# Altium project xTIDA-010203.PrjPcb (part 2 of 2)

## Sheet xTIDA-010203; CCMTLPFC_PowerStage.SchDoc
size A2; Date: Not shown in title block; ApprovedBy: Not shown in title block; CheckedBy: Not shown in title block; Author: Not shown in title block; CompanyName: Not shown in title block; Engineer: Not shown in title block; Organization: Not shown in title block; Address1: Not shown in title block; Address2: Not shown in title block; Address3: Not shown in title block; Address4: Not shown in title block; DocumentNumber: 2; Revision: Use project parameter SCH_Rev; SheetNumber: 2; SheetTotal: 4; PageSetup: Record=PageOptions¦CenterHorizontal=True¦CenterVertical=True¦PrintScale=1.00¦XCorrection=1.00¦YCorrection=1.00¦PrintKind=0¦BorderSize=5000000¦LeftOffset=0¦BottomOffset=0¦Orientation=2¦PaperLength=1000¦PaperWidth=1000¦Scale=100¦PaperSource=15¦PrintQuality=600¦MediaType=1¦DitherType=10¦PaperKind=Letter¦PrintScaleMode=1
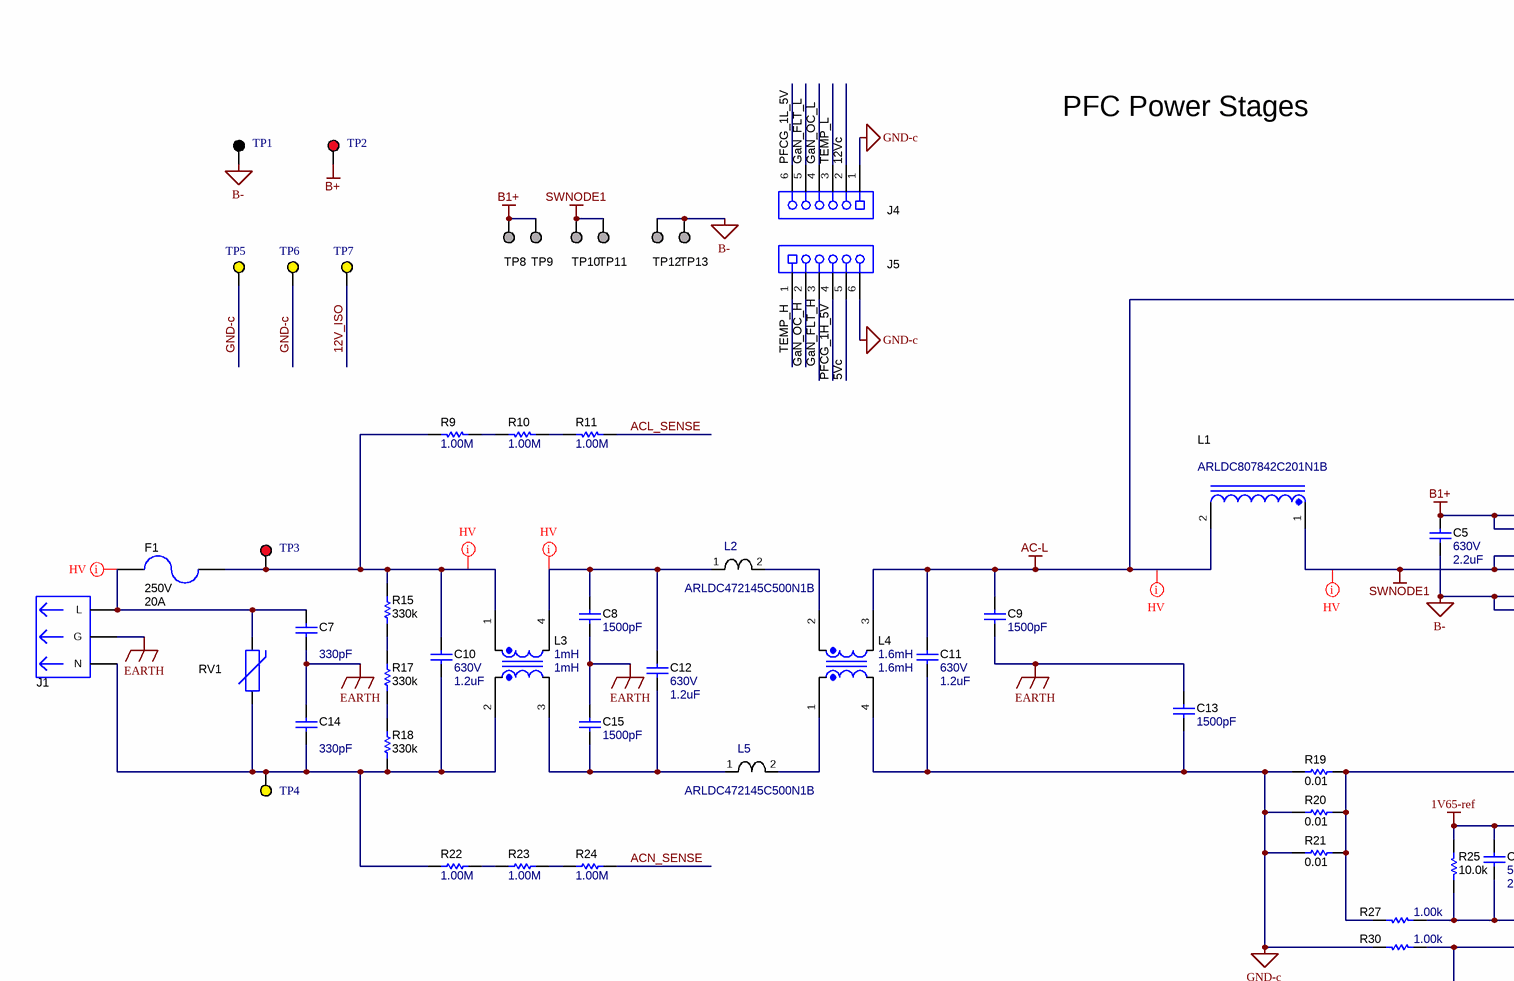
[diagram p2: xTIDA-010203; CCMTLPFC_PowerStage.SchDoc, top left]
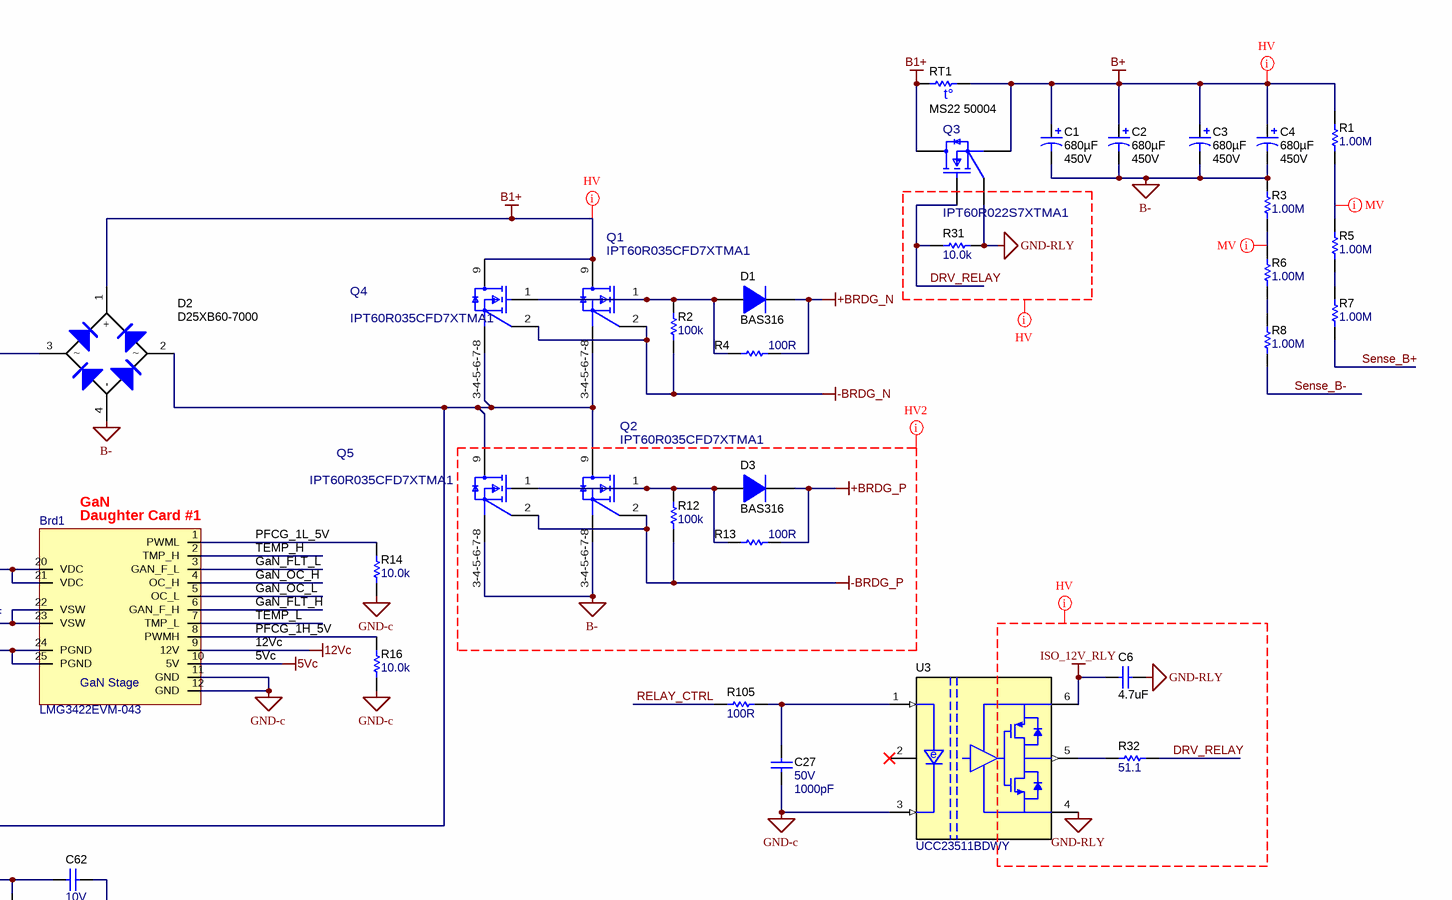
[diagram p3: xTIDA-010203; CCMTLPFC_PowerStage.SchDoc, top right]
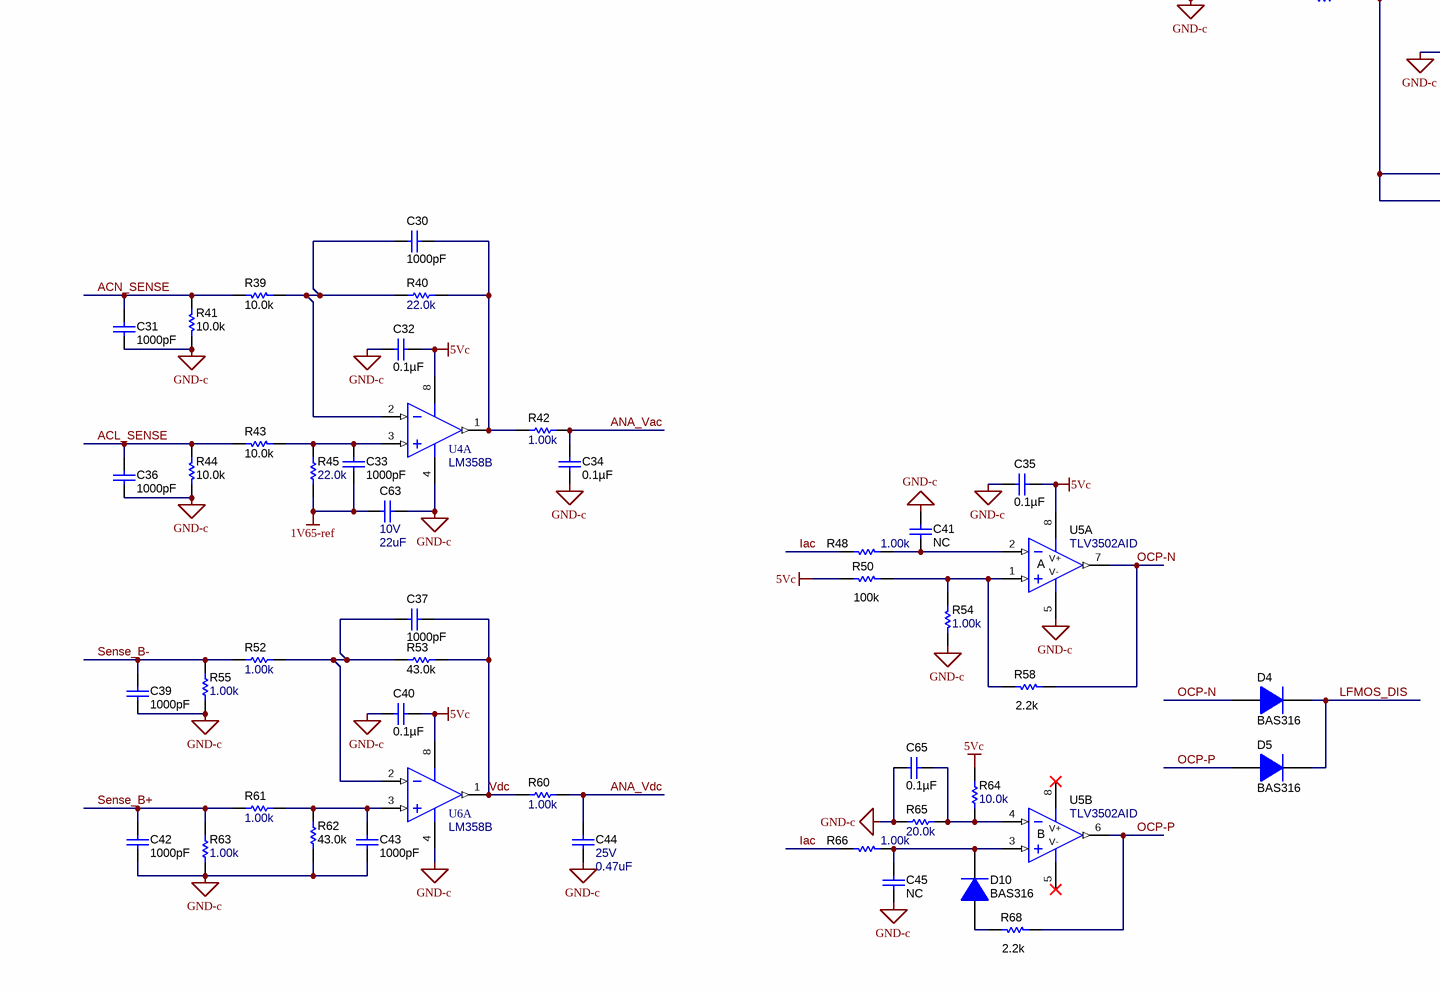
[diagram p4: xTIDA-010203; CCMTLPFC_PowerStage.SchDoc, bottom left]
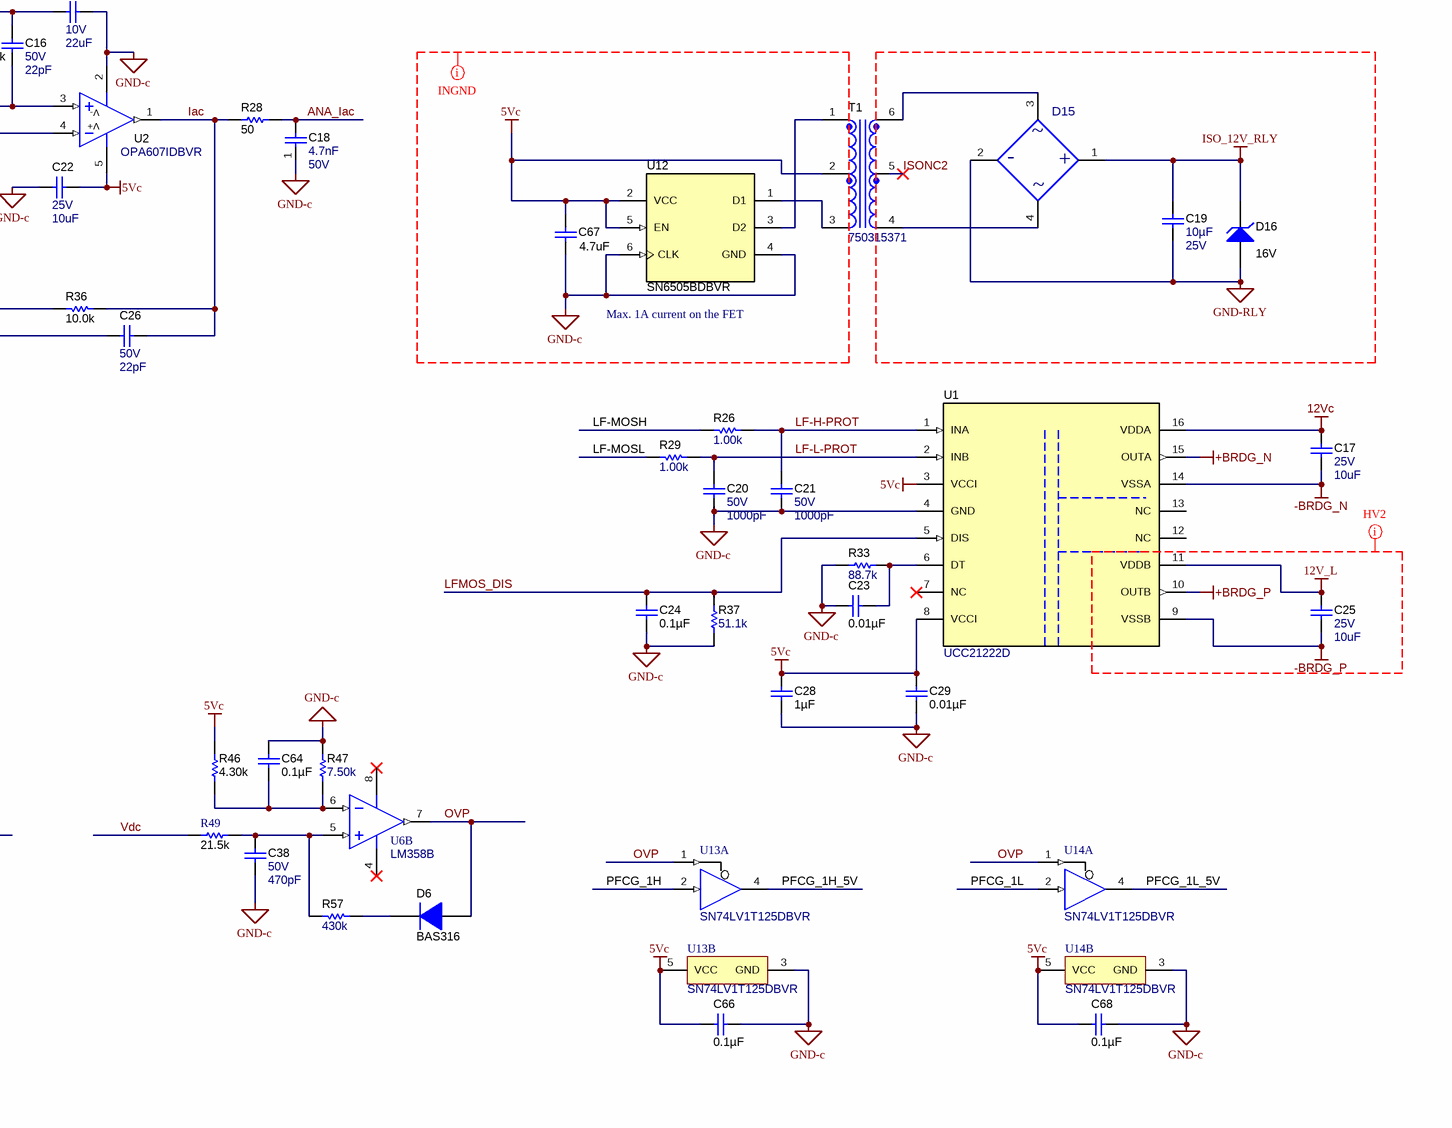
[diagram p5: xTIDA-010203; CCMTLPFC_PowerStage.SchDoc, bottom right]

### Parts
Brd1  LMG3422EVM-043  [HVP042E1]
C1  ValueDisplayed: 680µF  VDC_V: 450V  [WCAP-AI3H_3500x5700 - H]  (hidden comment: 450MXK680MEFCSN35X45)
C2  ValueDisplayed: 680µF  VDC_V: 450V  [WCAP-AI3H_3500x5700 - H]  (hidden comment: 450MXK680MEFCSN35X45)
C3  ValueDisplayed: 680µF  VDC_V: 450V  [WCAP-AI3H_3500x5700 - H]  (hidden comment: 450MXK680MEFCSN35X45)
C4  ValueDisplayed: 680µF  VDC_V: 450V  [WCAP-AI3H_3500x5700 - H]  (hidden comment: 450MXK680MEFCSN35X45)
C5  VDC_V: 630V  ValueDisplayed: 2.2uF  [B32924_24.5mm]  (hidden comment: ECWFG2J225)
C6  ValueDisplayed: 4.7uF  [0603]  (hidden comment: C1608X5R1V475K080AC)
C7  ValueDisplayed: 330pF  [KY_700x500x1000]  (hidden comment: DE2B3KY331KB3BU02F)
C8  ValueDisplayed: 1500pF  [CD45_800x600x1200]  (hidden comment: CD45-E2GA152M-NKA)
C9  ValueDisplayed: 1500pF  [CD45_800x600x1200]  (hidden comment: CD45-E2GA152M-NKA)
C10  VDC_V: 630V  ValueDisplayed: 1.2uF  [B32924_21.5mm]  (hidden comment: 890324027012)
C11  VDC_V: 630V  ValueDisplayed: 1.2uF  [B32924_21.5mm]  (hidden comment: 890324027012)
C12  VDC_V: 630V  ValueDisplayed: 1.2uF  [B32924_21.5mm]  (hidden comment: 890324027012)
C13  ValueDisplayed: 1500pF  [CD45_800x600x1200]  (hidden comment: CD45-E2GA152M-NKA)
C14  ValueDisplayed: 330pF  [KY_700x500x1000]  (hidden comment: DE2B3KY331KB3BU02F)
C15  ValueDisplayed: 1500pF  [CD45_800x600x1200]  (hidden comment: CD45-E2GA152M-NKA)
C16  VDC_V: 50V  ValueDisplayed: 22pF  [0603]  (hidden comment: CGA3E2C0G1H220J080AA)
C17  VDC_V: 25V  ValueDisplayed: 10uF  [0805_HV]  (hidden comment: GRM21BR61E106MA73L)
C18  Cap_F: 4.7nF  VDC_V: 50V  [0603]  (hidden comment: C0603C472J5RACTU)
C19  Cap_F: 10µF  VDC_V: 25V  [0805_HV]  (hidden comment: GRM21BZ71E106KE15L)
C20  VDC_V: 50V  ValueDisplayed: 1000pF  [0603]  (hidden comment: GCJ188R71H102KA01D)
C21  VDC_V: 50V  ValueDisplayed: 1000pF  [0603]  (hidden comment: GCJ188R71H102KA01D)
C22  VDC_V: 25V  ValueDisplayed: 10uF  [0805_HV]  (hidden comment: GRM21BR61E106MA73L)
C23  ValueDisplayed: 0.01µF  [0603]  (hidden comment: C0603X103K5RACTU)
C24  ValueDisplayed: 0.1µF  [0603]  (hidden comment: GRM188R71E104KA01D)
C25  VDC_V: 25V  ValueDisplayed: 10uF  [0805_HV]  (hidden comment: GRM21BR61E106MA73L)
C26  VDC_V: 50V  ValueDisplayed: 22pF  [0603]  (hidden comment: CGA3E2C0G1H220J080AA)
C27  VDC_V: 50V  ValueDisplayed: 1000pF  [0603]  (hidden comment: GCJ188R71H102KA01D)
C28  ValueDisplayed: 1µF  [0603]  (hidden comment: GRM185R60J105KE26D)
C29  ValueDisplayed: 0.01µF  [0603]  (hidden comment: C0603X103K5RACTU)
C30  ValueDisplayed: 1000pF  [0603]  (hidden comment: GRM188R71H102KA01D)
C31  ValueDisplayed: 1000pF  [0603]  (hidden comment: GRM188R71H102KA01D)
C32  ValueDisplayed: 0.1µF  [0603]  (hidden comment: GRM188R71E104KA01D)
C33  ValueDisplayed: 1000pF  [0603]  (hidden comment: GRM188R71H102KA01D)
C34  ValueDisplayed: 0.1µF  [0603]  (hidden comment: GRM188R71E104KA01D)
C35  ValueDisplayed: 0.1µF  [0603]  (hidden comment: GRM188R71E104KA01D)
C36  ValueDisplayed: 1000pF  [0603]  (hidden comment: GRM188R71H102KA01D)
C37  ValueDisplayed: 1000pF  [0603]  (hidden comment: GRM188R71H102KA01D)
C38  VDC_V: 50V  ValueDisplayed: 470pF  [0603]  (hidden comment: GRM188R71H471KA01D)
C39  ValueDisplayed: 1000pF  [0603]  (hidden comment: GRM188R71H102KA01D)
C40  ValueDisplayed: 0.1µF  [0603]  (hidden comment: GRM188R71E104KA01D)
C41  NC  [0603]  (no BOM)
C42  ValueDisplayed: 1000pF  [0603]  (hidden comment: GRM188R71H102KA01D)
C43  ValueDisplayed: 1000pF  [0603]  (hidden comment: GRM188R71H102KA01D)
C44  VDC_V: 25V  ValueDisplayed: 0.47uF  [0603]  (hidden comment: GRM188R61E474KA12D)
C45  NC  [0603]  (no BOM)
C62  VDC_V: 10V  ValueDisplayed: 22uF  [0603]  (hidden comment: C1608X5R1A226M080AC)
C63  VDC_V: 10V  ValueDisplayed: 22uF  [0603]  (hidden comment: C1608X5R1A226M080AC)
C64  ValueDisplayed: 0.1µF  [0603]  (hidden comment: GRM188R71E104KA01D)
C65  ValueDisplayed: 0.1µF  [0603]  (hidden comment: GRM188R71E104KA01D)
C66  ValueDisplayed: 0.1µF  [0603]  (hidden comment: GRM188R71E104KA01D)
C67  ValueDisplayed: 4.7uF  [0805_HV]  (hidden comment: GCM21BR71C475KA73L)
C68  ValueDisplayed: 0.1µF  [0603]  (hidden comment: GRM188R71E104KA01D)
D1  BAS316  [sod-323]
D2  D25XB60-7000  [5S]
D3  BAS316  [sod-323]
D4  BAS316  [sod-323]
D5  BAS316  [sod-323]
D6  BAS316  [sod-323]
D10  BAS316  [sod-323]
D15  KMB23STR  [FP-KMB23STR_SMT_4MM725_3MM85-MFG]  (value not drawn)
D16  value 16V  [SOD-123]  (hidden comment: BZT52C16-7-F)
F1  VAC_V: 250V  Irating_A: 20A  [FUSE_0325]  (hidden comment: 0325020.MXP)
J1  703W-00/54  [CONN_QUALTEK-703W-0054]  (value not drawn)  (mechanical)
J4  0448120024  [Molex_0448120024]  (value not drawn)
J5  0448120024  [Molex_0448120024]  (value not drawn)
L1  ARLDC807842C201N1B  [ARLDC807842C201N1B]
L2  ARLDC472145C500N1B  [ARLDC472145C500N1B]
L3  value 1mH  [ARCDC422740E102 N2B]  (hidden comment: ARCDC422740E102N2B)
L4  value 1.6mH  [ARCDC522747E152N2B]  (hidden comment: ARCDC522747E152N2B)
L5  ARLDC472145C500N1B  [ARLDC472145C500N1B]
Q1  IPT60R035CFD7XTMA1  [FP-IPT60R080G7XTMA1_HSOF-8-MFG]
Q2  IPT60R035CFD7XTMA1  [FP-IPT60R080G7XTMA1_HSOF-8-MFG]
Q3  IPT60R022S7XTMA1  [FP-IPT60R080G7XTMA1_HSOF-8-MFG]
Q4  IPT60R035CFD7XTMA1  [FP-IPT60R080G7XTMA1_HSOF-8-MFG]
Q5  IPT60R035CFD7XTMA1  [FP-IPT60R080G7XTMA1_HSOF-8-MFG]
R1  ValueDisplayed: 1.00M  [1206]  (hidden comment: RCV12061M00FKEA)
R2  ValueDisplayed: 100k  [0603]  (hidden comment: RC0603FR-07100KL)
R3  ValueDisplayed: 1.00M  [1206]  (hidden comment: RCV12061M00FKEA)
R4  ValueDisplayed: 100R  [0603]  (hidden comment: 100R 0603)
R5  ValueDisplayed: 1.00M  [1206]  (hidden comment: RCV12061M00FKEA)
R6  ValueDisplayed: 1.00M  [1206]  (hidden comment: RCV12061M00FKEA)
R7  ValueDisplayed: 1.00M  [1206]  (hidden comment: RCV12061M00FKEA)
R8  ValueDisplayed: 1.00M  [1206]  (hidden comment: RCV12061M00FKEA)
R9  ValueDisplayed: 1.00M  [1206]  (hidden comment: RCV12061M00FKEA)
R10  ValueDisplayed: 1.00M  [1206]  (hidden comment: RCV12061M00FKEA)
R11  ValueDisplayed: 1.00M  [1206]  (hidden comment: RCV12061M00FKEA)
R12  ValueDisplayed: 100k  [0603]  (hidden comment: RC0603FR-07100KL)
R13  ValueDisplayed: 100R  [0603]  (hidden comment: 100R 0603)
R14  ValueDisplayed: 10.0k  [0603]  (hidden comment: ERJ-3EKF1002V)
R15  ValueDisplayed: 330k  [1206]  (hidden comment: RV1206FR-07330KL)
R16  ValueDisplayed: 10.0k  [0603]  (hidden comment: ERJ-3EKF1002V)
R17  ValueDisplayed: 330k  [1206]  (hidden comment: RV1206FR-07330KL)
R18  ValueDisplayed: 330k  [1206]  (hidden comment: RV1206FR-07330KL)
R19  ValueDisplayed: 0.01  [1206]  (hidden comment: WSLP1206R0100FEA)
R20  ValueDisplayed: 0.01  [1206]  (hidden comment: WSLP1206R0100FEA)
R21  ValueDisplayed: 0.01  [1206]  (hidden comment: WSLP1206R0100FEA)
R22  ValueDisplayed: 1.00M  [1206]  (hidden comment: RCV12061M00FKEA)
R23  ValueDisplayed: 1.00M  [1206]  (hidden comment: RCV12061M00FKEA)
R24  ValueDisplayed: 1.00M  [1206]  (hidden comment: RCV12061M00FKEA)
R25  ValueDisplayed: 10.0k  [0603]  (hidden comment: CRCW060310K0FKEA)
R26  ValueDisplayed: 1.00k  [0603]  (hidden comment: ERJ-3EKF1001V)
R27  ValueDisplayed: 1.00k  [0603]  (hidden comment: ERJ-3EKF1001V)
R28  ValueDisplayed: 50  [0603]  (hidden comment: CRCW060350R0FKEA)
R29  ValueDisplayed: 1.00k  [0603]  (hidden comment: ERJ-3EKF1001V)
R30  ValueDisplayed: 1.00k  [0603]  (hidden comment: ERJ-3EKF1001V)
R31  ValueDisplayed: 10.0k  [0603]  (hidden comment: ERJ-3EKF1002V)
R32  ValueDisplayed: 51.1  [0603]  (hidden comment: RC0603FR-0751R1L)
R33  ValueDisplayed: 88.7k  [0603]  (hidden comment: CRCW060388K7FKEA)
R36  ValueDisplayed: 10.0k  [0603]  (hidden comment: CRCW060310K0FKEA)
R37  ValueDisplayed: 51.1k  [0603]  (hidden comment: RC0603FR-0751K1L)
R39  ValueDisplayed: 10.0k  [0603]  (hidden comment: CRCW060310K0FKEA)
R40  ValueDisplayed: 22.0k  [0603]  (hidden comment: ERJ-3EKF2202V)
R41  ValueDisplayed: 10.0k  [0603]  (hidden comment: CRCW060310K0FKEA)
R42  ValueDisplayed: 1.00k  [0603]  (hidden comment: ERJ-3EKF1001V)
R43  ValueDisplayed: 10.0k  [0603]  (hidden comment: CRCW060310K0FKEA)
R44  ValueDisplayed: 10.0k  [0603]  (hidden comment: CRCW060310K0FKEA)
R45  ValueDisplayed: 22.0k  [0603]  (hidden comment: ERJ-3EKF2202V)
R46  ValueDisplayed: 4.30k  [0603]  (hidden comment: RC0603FR-074K3L)
R47  ValueDisplayed: 7.50k  [0603]  (hidden comment: ERJ-3EKF7501V)
R48  ValueDisplayed: 1.00k  [0603]  (hidden comment: ERJ-3EKF1001V)
R49  value 21.5k  [0603]  (hidden comment: CRCW060321K5FKEA)
R50  100k  [0603]
R52  ValueDisplayed: 1.00k  [0603]  (hidden comment: CRCW06031K00FKEA)
R53  ValueDisplayed: 43.0k  [0603]  (hidden comment: RC0603FR-0743KL)
R54  ValueDisplayed: 1.00k  [0603]  (hidden comment: ERJ-3EKF1001V)
R55  ValueDisplayed: 1.00k  [0603]  (hidden comment: CRCW06031K00FKEA)
R57  ValueDisplayed: 430k  [0603]  (hidden comment: RC0603FR-07430KL)
R58  2.2k  [0603]
R60  ValueDisplayed: 1.00k  [0603]  (hidden comment: ERJ-3EKF1001V)
R61  ValueDisplayed: 1.00k  [0603]  (hidden comment: CRCW06031K00FKEA)
R62  ValueDisplayed: 43.0k  [0603]  (hidden comment: RC0603FR-0743KL)
R63  ValueDisplayed: 1.00k  [0603]  (hidden comment: CRCW06031K00FKEA)
R64  ValueDisplayed: 10.0k  [0603]  (hidden comment: ERJ-3EKF1002V)
R65  ValueDisplayed: 20.0k  [0603]  (hidden comment: RC0603FR-0720KL)
R66  ValueDisplayed: 1.00k  [0603]  (hidden comment: ERJ-3EKF1001V)
R68  2.2k  [0603]
R105  ValueDisplayed: 100R  [0603]  (hidden comment: 100R 0603)
RT1  MS22 50004  [MS2250004]
RV1  S10K275E2  [VAR_S10K275E2]  (value not drawn)
T1  750315371  [Wurth_750315371]
TP1  5001  [Keystone5001]  (value not drawn)  (no BOM)
TP2  5000  [Keystone5000]  (value not drawn)  (no BOM)
TP3  5000  [Keystone5000]  (value not drawn)  (no BOM)
TP4  5004  [Keystone5004]  (value not drawn)  (no BOM)
TP5  5004  [Keystone5004]  (value not drawn)  (no BOM)
TP6  GNDc  [Keystone5004]  (value not drawn)  (no BOM)
TP7  12Vc  [Keystone5004]  (value not drawn)  (no BOM)
TP8  Suggest using a net name here  [Mill-Max_0312-0-15-15-34-27-10-0]  (value not drawn)
TP9  Suggest using a net name here  [Mill-Max_0312-0-15-15-34-27-10-0]  (value not drawn)
TP10  Suggest using a net name here  [Mill-Max_0312-0-15-15-34-27-10-0]  (value not drawn)
TP11  Suggest using a net name here  [Mill-Max_0312-0-15-15-34-27-10-0]  (value not drawn)
TP12  Suggest using a net name here  [Mill-Max_0312-0-15-15-34-27-10-0]  (value not drawn)
TP13  Suggest using a net name here  [Mill-Max_0312-0-15-15-34-27-10-0]  (value not drawn)
U1  PartNumber: UCC21222D  [D0016A_N]  (hidden comment: UCC21222AD)
U2  OPA607IDBVR  [DBV0005A_N]
U3  UCC23511BDWY  [DWY0006A]
U4  LM358B  [D0008A_N]  (part A of 2)
U5  TLV3502AID  [D0008A_N]  (parts A,B of 2)
U6  PartNumber: LM358B  [D0008A_N]  (hidden comment: LM358AM)  (parts A,B of 2)
U12  SN6505BDBVR  [DBV0006A_N]
U13  SN74LV1T125DBVR  [DBV0005A_N]  (parts A,B of 2)
U14  SN74LV1T125DBVR  [DBV0005A_N]  (parts A,B of 2)

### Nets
1V65-ref: C16.1 C33.2 C62.1 C63.1 R25.2 R45.2
5Vc: Brd1.10(5V) C22.2 C28.1 C29.1 C32.2 C35.2 C40.2 C66.1 C67.1 C68.1 J5.5 R46.2 R50.1 R64.2 T1.2 U1.3(VCCI) U1.8(VCCI) U2.5(V+) U4.8(V+) U5.8(V+) U6.8(V+) U12.2(VCC) U12.5(EN) U13.5(VCC) U14.5(VCC)
12V_L: C25.1 U1.11(VDDB)
12Vc: Brd1.9(12V) C17.1 J4.2 U1.16(VDDA)
+BRDG_N: D1.1(K) R4.1 U1.15(OUTA)
+BRDG_P: D3.1(K) R13.1 U1.10(OUTB)
-BRDG_N: C17.2 Q1.2(Driver_Source) Q4.2(Driver_Source) R2.1 U1.14(VSSA)
-BRDG_P: C25.2 Q2.2(Driver_Source) Q5.2(Driver_Source) R12.1 U1.9(VSSB)
AC-L: C9.1 C11.1 D2.3 L1.2 L4.3
B1+: Brd1.20(VDC) Brd1.21(VDC) C5.1 D2.1(+) Q1.9(Drain) Q3.9(Drain) Q4.9(Drain) RT1.1 TP8.1 TP9.1
B+: C1.1(+) C2.1(+) C3.1(+) C4.1(+) Q3.3-4-5-6-7-8(Source) R1.2 RT1.2 TP2.1
B-: Brd1.24(PGND) Brd1.25(PGND) C1.2(-) C2.2(-) C3.2(-) C4.2(-) C5.2 D2.4(-) Q2.3-4-5-6-7-8(Source) Q5.3-4-5-6-7-8(Source) R3.2 TP1.1 TP12.1 TP13.1
EARTH: C7.2 C8.2 C9.2 C13.1 C14.1 C15.1 J1.3(G)
GND-c: Brd1.11(GND) Brd1.12(GND) C11.2 C13.2 C18.1 C20.2 C21.1 C22.1 C23.2 C24.1 C27.1 C28.2 C29.2 C31.2 C32.1 C34.1 C35.1 C36.2 C38.2 C39.2 C40.1 C41.2 C42.2 C43.1 C44.1 C45.1 C62.2 C63.2 C64.1 C65.2 C66.2 C67.2 C68.2 J4.1 J5.6 L4.4 R14.2 R16.2 R19.1 R20.1 R21.1 R30.2 R33.2 R37.1 R41.1 R44.1 R47.2 R54.2 R55.2 R62.1 R63.1 R65.2 TP5.1 TP6.1 U1.4(GND) U2.2(V-) U3.3(Cathode) U4.4(GND) U5.5(V-) U6.4(GND) U12.4(GND) U12.6(CLK) U13.3(GND) U14.3(GND)
GND-RLY: C6.2 C19.2 D15.2(-) D16.2(A) Q3.2(Driver_Source) R31.1 U3.4(VSS)
ISO_12V_RLY: C6.1 C19.1 D15.1(+) D16.1(K) U3.6(Vout)
SWNODE1: Brd1.22(VSW) Brd1.23(VSW) L1.1 TP10.1 TP11.1
12V_ISO: TP7.1
ACL_SENSE: C36.1 R11.2 R43.1 R44.2
ACN_SENSE: C31.1 R24.2 R39.1 R41.2
ANA_Iac: C18.2 R28.2
ANA_Vac: C34.2 R42.1
ANA_Vdc: C44.2 R60.1
DRV_RELAY: Q3.1(Gate) R31.2 R32.2
GaN_FLT_H: Brd1.6(GAN_F_H) J5.3
GaN_FLT_L: Brd1.3(GAN_F_L) J4.5
GaN_OC_H: Brd1.4(OC_H) J5.2
GaN_OC_L: Brd1.5(OC_L) J4.4
Iac: C26.1 R28.1 R36.1 R48.2 R66.2 U2.1(OUT)
ISONC2: T1.5
LF-H-PROT: C21.2 R26.1 U1.1(INA)
LF-L-PROT: C20.1 R29.1 U1.2(INB)
LF-MOSH: R26.2
LF-MOSL: R29.2
LFMOS_DIS: C24.2 D4.1(K) D5.1(K) R37.2 U1.5(DIS)
OCP-N: D4.2(A) R58.2 U5.7(OUT_A)
OCP-P: D5.2(A) R68.2 U5.6(OUT_B)
OVP: D6.2(A) U6.7(OUTB) U13.1(~{OE}) U14.1(~{OE})
PFCG_1H: U13.2(A)
PFCG_1H_5V: Brd1.8(PWMH) J5.4 R16.1 U13.4(Y)
PFCG_1L: U14.2(A)
PFCG_1L_5V: Brd1.1(PWML) J4.6 R14.1 U14.4(Y)
RELAY_CTRL: R105.2
Sense_B+: C42.1 R7.1 R61.1 R63.2
Sense_B-: C39.1 R8.1 R52.2 R55.1
TEMP_H: Brd1.2(TMP_H) J5.1
TEMP_L: Brd1.7(TMP_L) J4.3
Vdc: C37.2 R49.2 R53.2 R60.2 U6.1(OUTA)
NetC7_1: C7.1 F1.2 J1.1(L) RV1.2
NetC8_1: C8.1 C12.1 L2.1 L3.4
NetC10_1: C10.1 F1.1 L3.1 R9.1 R15.2 TP3.1
NetC10_2: C10.2 C14.2 J1.2(N) L3.2 R18.1 R22.1 RV1.1 TP4.1
NetC12_2: C12.2 C15.2 L3.3 L5.1
NetC16_2: C16.2 R25.1 R27.1 U2.3(IN+)
NetC23_1: C23.1 R33.1 U1.6(DT)
NetC26_2: C26.2 R30.1 R36.2 U2.4(IN-)
NetC27_2: C27.2 R105.1 U3.1(Anode)
NetC30_1: C30.1 R39.2 R40.2 U4.2(INA-)
NetC30_2: C30.2 R40.1 R42.2 U4.1(OUTA)
NetC33_1: C33.1 R43.2 R45.1 U4.3(INA+)
NetC37_1: C37.1 R52.1 R53.1 U6.2(INA-)
NetC38_1: C38.1 R49.1 R57.2 U6.5(INB+)
NetC41_1: C41.1 R48.1 U5.2(-IN_A)
NetC43_2: C43.2 R61.2 R62.2 U6.3(INA+)
NetC45_2: C45.2 D10.1(K) R66.1 U5.3(+IN_B)
NetC64_2: C64.2 R46.1 R47.1 U6.6(INB-)
NetC65_1: C65.1 R64.1 R65.1 U5.4(-IN_B)
NetD1_2: D1.2(A) Q1.1(Gate) Q4.1(Gate) R2.2 R4.2
NetD2_2: D2.2 Q1.3-4-5-6-7-8(Source) Q2.9(Drain) Q4.3-4-5-6-7-8(Source) Q5.9(Drain) R19.2 R20.2 R21.2 R27.2
NetD3_2: D3.2(A) Q2.1(Gate) Q5.1(Gate) R12.2 R13.2
NetD6_1: D6.1(K) R57.1
NetD10_2: D10.2(A) R68.1
NetD15_3: D15.3(1_~) T1.6
NetD15_4: D15.4(2_~) T1.4
NetL2_2: L2.2 L4.2
NetL4_1: L4.1 L5.2
NetR1_1: R1.1 R5.2
NetR3_1: R3.1 R6.2
NetR5_1: R5.1 R7.2
NetR6_1: R6.1 R8.2
NetR9_2: R9.2 R10.1
NetR10_2: R10.2 R11.1
NetR15_1: R15.1 R17.2
NetR17_1: R17.1 R18.2
NetR22_2: R22.2 R23.1
NetR23_2: R23.2 R24.1
NetR32_1: R32.1 U3.5(Vout)
NetR50_2: R50.2 R54.1 R58.1 U5.1(+IN_A)
NetT1_1: T1.1 U12.3(D2)
NetT1_3: T1.3 U12.1(D1)

Not connected (* = marked no-connect by the designer): U1 7(NC)* 12(NC) 13(NC); U3 2(NC)*

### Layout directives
net class HV: AC-L, B1+, B+, NetC7_1, NetC8_1, NetC10_1, SWNODE1
net class MV: 12V_L, +BRDG_P, -BRDG_P, B-, DRV_RELAY, GND-RLY, ISO_12V_RLY, NetR1_1, NetR3_1
net class INGND: 5Vc, GND-c

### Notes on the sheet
- PFC Power Stages
- (near Brd1) GaN
- (near Brd1) Daughter Card #1
- Max. 1A current on the FET

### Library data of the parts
Brd1 = Brd- GaN: GaN daughter card with LMG342xR030; Manufacturer: TEXAS INSTRUMENTS; SymbolCreator: Use LDAP id; SymbolVersion: use current date i.e. 2008-05-20
C1-C4 = CMP-0084882-1: CAP, AL, 680 µF, 450 V, +/- 20%, TH; Manufacturer: Rubycon; SizeY_mm: 35; CompType: Capacitor; U/M: EA; SizeZ_mm: 45; SizeAreaWB_mm2: 1369; SizeArea_mm2: 1225; TaMax_C: 105°C; AEC Category: Q200; Cap_Case: 35x57mm; TaMin_C: -25°C; AEC Qualified: N; Value: 680uF; Polarized: Y
C5 = CMP-0012436-3: CAP, Film, 2.2 uF, 630 V, +/- 20%, TH; Manufacturer: Panasonic; Polarized: N; SizeAreaWB_mm2: 536; Value1: Unknown; Value: 2.2uF; TaMax_C: 110°C; SizeZ_mm: 24.5; SizeX_mm: 12; SizeY_mm: 31.5; SizeArea_mm2: 441; Cap_F: 2.2µF; AEC Category: Q200
C6 = CMP-0007022-5: CAP, CERM, 4.7 uF, 35 V, +/- 10%, X5R, 0603; Manufacturer: TDK; TaMin_C: -55°C; ESR_ohm: 3.728m; Polarized: N; SizeAreaWB_mm2: 4.68; Value1: 0.003728 ohm; U/M: EA; Value: 4.7uF; TaMax_C: 85°C; SizeZ_mm: 1; SizeX_mm: 1.6; SizeY_mm: 0.8; Value2: 35V; SizeArea_mm2: 1.28; CompType: Capacitor; Cap_F: 4.7µF; IRMS_A: 2.69359A; AEC Category: Q200
C7 C14 = CMP-0009608-4: CAP, CERM, 330 pF, X1 250 VAC/Y2 300 VAC, +/- 10%, B, TH; Manufacturer: MuRata; TaMin_C: -25°C; Polarized: N; SizeAreaWB_mm2: 66.5; Value1: Unknown; U/M: EA; Value: 330pF; TaMax_C: 85°C; SizeZ_mm: 10; SizeX_mm: 7.5; SizeY_mm: 5; Cap_Case: 7x5x10mm; SizeArea_mm2: 37.5; AEC Category: Q200; AC_Safety: X1Y2; VAC_X: 250V; VAC_Y: 300V
C8 C9 C13 C15 = CMP-0009596-2: CAP, CERM, 1500 pF,  V, +/- 20%, E, D8xT6mm; Manufacturer: TDK; TaMin_C: -25°C; Polarized: N; SizeAreaWB_mm2: 101.2; Value1: Unknown; U/M: EA; Value: 1500pF; TaMax_C: 125°C; SizeZ_mm: 12; SizeX_mm: 10.65; SizeY_mm: 6; Cap_Case: 8x6x12mm; SizeArea_mm2: 63.9; Cap_F: 1.5nF; AEC Category: Q200
C10-C12 = CMP-0012433-1: CAP, Film, 1.2 uF, 630 V, +/- 10%, 0.017 ohm, TH; Manufacturer: Wurth Elktronik; ESR_ohm: 0.017; Polarized: N; SizeAreaWB_mm2: 485.75; U/M: EA; Value: 1.2uF; TaMax_C: 110°C; SizeZ_mm: 21.5; SizeX_mm: 12.5; SizeY_mm: 31.5; SizeArea_mm2: 393.75; Cap_F: 1.2µF; IRMS_A: 146mA; AEC Category: Q200
C16 C26 = CMP-0007071-1: CAP, CERM, 22 pF, 50 V, +/- 5%, C0G/NP0, AEC-Q200 Grade 1, 0603; Manufacturer: TDK; TaMin_C: -55°C; Polarized: N; SizeAreaWB_mm2: 4.68; Value1: Unknown; U/M: EA; Value: 22pF; TaMax_C: 125°C; SizeZ_mm: 1; SizeX_mm: 1.6; SizeY_mm: 0.8; SizeArea_mm2: 1.28; AEC Qualified: Y; AEC Category: Q200
C17 C22 C25 = CMP-0008378-2: CAP, CERM, 10 uF, 25 V, +/- 10%, X5R, 0805; Manufacturer: MuRata; TaMin_C: -55°C; Polarized: N; SizeAreaWB_mm2: 6.75; Value1: Unknown; U/M: EA; Value: 10uF; TaMax_C: 85°C; SizeZ_mm: 1.45; SizeX_mm: 2; SizeY_mm: 1.25; Cap_Case: 0805; SizeArea_mm2: 2.5; Cap_F: 10µF; AEC Category: Q200
C18 = CMP-0006942-1: CAP, CERM, 4700 pF, 50 V, +/- 5%, X7R, 0603; Manufacturer: Kemet; TaMin_C: -55°C; Polarized: N; SizeAreaWB_mm2: 4.68; Value1: Unknown; U/M: EA; Value: 4700pF; TaMax_C: 125°C; SizeZ_mm: 1; SizeX_mm: 1.6; SizeY_mm: 0.8; SizeArea_mm2: 1.28; AEC Category: Q200
C19 = CMP-0008378-1: CAP, CERM, 10 uF, 25 V, +/- 10%, X7R, 0805; Manufacturer: MuRata; TaMin_C: -55°C; Polarized: N; SizeAreaWB_mm2: 6.75; Value1: Unknown; U/M: EA; Value: 10uF; TaMax_C: 125°C; SizeZ_mm: 1.45; SizeX_mm: 2; SizeY_mm: 1.25; Cap_Case: 0805; SizeArea_mm2: 2.5; AEC Category: Q200
C20 C21 C27 = CMP-0007432-5: CAP, CERM, 1000 pF, 50 V, +/- 10%, X7R, 0603; Manufacturer: MuRata; TaMin_C: -55°C; Polarized: N; SizeAreaWB_mm2: 4.68; Value1: Unknown; U/M: EA; Value: 1000pF; TaMax_C: 125°C; SizeZ_mm: 1; SizeX_mm: 1.6; SizeY_mm: 0.8; SizeArea_mm2: 1.28; Cap_F: 1nF; AEC Category: Q200
C23 C29 = C0603X103K5RACTU: CAP, CERM, 0.01uF, 50V, +/-10%, X7R, 0603; Manufacturer: Kemet; Polarized: N; CompType: Capacitor; U/M: EA; Cap_F: 0.00000001; Tolerance_%: 10; Value1: Unknown; VDC_V: 50; TaMin_C: -55; TaMax_C: 125
C24 C32 C34 C35 C40 C41 C45 C64-C66 C68 = GRM188R71E104KA01D: CAP, CERM, 0.1 µF, 25 V,+/- 10%, X7R, 0603; Manufacturer: MuRata; Polarized: N; CompType: Capacitor; Value: 0.1uF; U/M: EA; Cap_F: 0.0000001; Tolerance_%: 10; VDC_V: 25; Value2: 25V; TaMin_C: -55; TaMax_C: 125; SizeArea_mm2: 1.28; SizeAreaWB_mm2: 4.68; SizeX_mm: 1.6; SizeY_mm: 0.8; SizeZ_mm: 1; AEC Category: Q200; Green_Lifecycle: Active; Green_REACh: Passed
C28 = GRM185R60J105KE26D: CAP, CERM, 1uF, 6.3V, +/-10%, X5R, 0603; Manufacturer: MuRata; Polarized: N; CompType: Capacitor; U/M: EA; Cap_F: 0.000001; Tolerance_%: 10; Value1: Unknown; VDC_V: 6.3; TaMin_C: -55; TaMax_C: 85
C30 C31 C33 C36 C37 C39 C42 C43 = GRM188R71H102KA01D: CAP, CERM, 1000 pF, 50 V,+/- 10%, X7R, 0603; Manufacturer: MuRata; Polarized: N; CompType: Capacitor; Value: 1000pF; U/M: EA; Cap_F: 0.000000001; Tolerance_%: 10; VDC_V: 50; Value2: 50V; TaMin_C: -55; TaMax_C: 125; SizeArea_mm2: 1.28; SizeAreaWB_mm2: 4.68; SizeX_mm: 1.6; SizeY_mm: 0.8; SizeZ_mm: 1; AEC Category: Q200; Green_Lifecycle: Active; Green_REACh: Passed
C38 = CMP-0007455-4: CAP, CERM, 470 pF, 50 V, +/- 10%, X7R, 0603; Manufacturer: MuRata; TaMin_C: -55°C; Polarized: N; SizeAreaWB_mm2: 4.68; Value1: Unknown; U/M: EA; Value: 470pF; TaMax_C: 125°C; SizeZ_mm: 1; SizeX_mm: 1.6; SizeY_mm: 0.8; SizeArea_mm2: 1.28; AEC Category: Q200
C44 = CMP-0007346-2: CAP, CERM, 0.47 uF, 25 V, +/- 10%, X5R, 0603; Manufacturer: MuRata; TaMin_C: -55°C; Polarized: N; SizeAreaWB_mm2: 4.68; Value1: Unknown; U/M: EA; Value: 0.47uF; TaMax_C: 85°C; SizeZ_mm: 1; SizeX_mm: 1.6; SizeY_mm: 0.8; SizeArea_mm2: 1.28; Cap_F: 470nF; AEC Category: Q200
C62 C63 = CMP-0007005-1: CAP, CERM, 22 uF, 10 V, +/- 20%, X5R, 0603; Manufacturer: TDK; TaMin_C: -55°C; ESR_ohm: 3.71m; Polarized: N; SizeAreaWB_mm2: 4.68; Value1: 0.00371 ohm; U/M: EA; Value: 22uF; TaMax_C: 85°C; SizeZ_mm: 1; SizeX_mm: 1.6; SizeY_mm: 0.8; SizeArea_mm2: 1.28; Cap_F: 22µF; IRMS_A: 2.69936A; AEC Category: Q200
C67 = CMP-0008020-2: CAP, CERM, 4.7 uF, 16 V, +/- 10%, X7R, AEC-Q200 Grade 1, 0805; Manufacturer: MuRata; TaMin_C: -55°C; Polarized: N; SizeAreaWB_mm2: 6.75; Value1: Unknown; U/M: EA; Value: 4.7uF; TaMax_C: 125°C; SizeZ_mm: 1.45; SizeX_mm: 2; SizeY_mm: 1.25; Cap_Case: 0805; Value2: 16V; SizeArea_mm2: 2.5; AEC Qualified: Y; Cap_F: 4.7µF; AEC Grade: 1; AEC Category: Q200
D1 D3-D6 D10 = BAS316,115: Diode, Ultrafast, 100 V, 0.25 A, SOD-323; Manufacturer: Toshiba; U/M: EA; Vf_V: 1.4; Value: 100V; Value1: 0.25A; Value2: 1.4V; Io_A: 0.25; Vr_V: 100; TJmax_C: 150
D2 = D25XB60-7000: Diode, Switching-Bridge, 800 V, 25 A, TH; Manufacturer: Shindengen; U/M: EA; Vf_V: 1.05; Value: 600V; Value1: 3.5A; Value2: 1.05V; Io_A: 3.5; Vr_V: 600; TJmax_C: 150
D15 = CMP-0089345-2: Bridge Rectifier Single Phase Schottky 30V Surface Mount MBS; Manufacturer: SMC; TJmax_C: 150°C; Cap_F: 28pF; Max Surge Forward Current: 50A; Forward Current: 2A; Peak Reverse Current: 0.1mA; CompType: Diode; Standoff Height: 0.2mm; AEC Category: Q101; SizeZ_mm: 2.9mm; AEC Qualified: No
D16 = CMP-0005769-2: Diode, Zener, 16 V, 500 mW, AEC-Q101, SOD-123; Manufacturer: Diodes Inc.; Power_W: 500mW; SizeAreaWB_mm2: 13.095; Value1: 0.5W; RJA_CperW: 338; U/M: EA; SizeZ_mm: 1.35; SizeX_mm: 3.85; SizeY_mm: 1.7; SizeArea_mm2: 6.545; AEC Qualified: Y; AEC Category: Q101
F1 = 0325020.MXP: Fuse, 20 A, 250 VAC, 60 VDC, TH; Manufacturer: Littelfuse; VDC_V: 60; Interrupt_AC: 400; Rtyp_Ohm: 0.0034; MeltingTyp: 575
J1 = 703W-00/54: AC Receptacle, 10A 250VAC; Manufacturer: Qualtek Electronics Corporation; SymbolCreator: a0799628; CompType: Connector; U/M: EA
J4 J5 = 0448120024: Receptacle, 2.54mm, 6x1, Gold, TH; Manufacturer: Molex; SymbolCreator: a0411947; Pitch_mm: 2.54; Gender: Female; Row_Count: 1
L1 = CHOKE_PQ35: PFC CHOKE 480uH 33A; Manufacturer: Sunlord; Green_REACh: Incomplete; CompType: Transformer; Green_Lifecycle: Not Set; SizeX_mm: 30; SizeY_mm: 22; SizeZ_mm: 34; Value: 300uH
L2 L5 = ARLDC472145C500N1B: DM CHOKE; Manufacturer: Sunlord; SymbolCreator: Use LDAP id; SymbolVersion: use current date i.e. 2008-05-20
L3 = INDUCTOR_COUPLED_14_23: Coupled inductor, 2x 1.01 mH, 2 x 0.0022ohm, 1650V TH; Manufacturer: Sunlord; SizeAreaWB_mm2: 513; DCR_ohm: 0.012; SizeZ_mm: 25; SizeX_mm: 23; SizeY_mm: 17; SizeArea_mm2: 425; Ind_H: 2mH
L4 = CMP-0013122-2: Coupled inductor, 2x 1.6 mH, 2 x 0.0022ohm, 1650V TH; Manufacturer: Sunlord; SizeAreaWB_mm2: 513; DCR_ohm: 0.012; SizeZ_mm: 32; SizeX_mm: 25; SizeY_mm: 20; SizeArea_mm2: 425
Q1 Q2 Q4 Q5 = CMP-0086487-1: MOSFET N-CH 600V 67A 8HSOF; Manufacturer: Infineon; QgTyp_nC: 42nC @ 10V; Rdson45_ohm: 0.069; VdsMax_V: 650V; IdsMax_A: 123A; Vgs_V: 20V; AEC Qualified: No; ChMode: False; SizeZ_mm: 2.4mm
Q3 = CMP-0086487-1: MOSFET N-CH 650V 23A HSOF-8; Manufacturer: Infineon; QgTyp_nC: 42nC @ 10V; Rdson45_ohm: 0.069; IdsMax_A: 123A; Vgs_V: 20V; AEC Qualified: No; ChMode: False; SizeZ_mm: 2.4mm
R1 R3 R5-R11 R22-R24 = CMP-0017798-2: RES SMD 1M OHM 1% 1/4W 1206; Manufacturer: Vishay Dale; Power_W: 250mW; TempCo: 100 ppm/C; Value_Code: 1M00; U/M: EA; Value: 1.00Meg; EIA_Code: E96; SizeX_mm: 3.2; SizeY_mm: 1.6; SizeZ_mm: 1.35; Value2: 0.25W; SizeArea_mm2: 5.12; VDC_V: 200V; AEC Category: Q200
R2 R12 = CMP-0022735-5: RES, 100 k, 1%, 0.1 W, 0603; Manufacturer: Yageo; Power_W: 100mW; TempCo: 100 ppm/C; Value: 100k; EIA_Code: E96; SizeX_mm: 1.6; SizeY_mm: 0.8; SizeZ_mm: 1; Value2: 0.1W; SizeArea_mm2: 1.28; AEC Qualified: N; VDC_V: 75V; AEC Category: Q200; SizeAreaWB_mm2: 4.68
R4 R13 R105 = CMP-0023198-5: RES, 100R, 1%, 0.1 W, 0603; Manufacturer: Yageo; Power_W: 100mW; TempCo: 100 ppm/C; SizeX_mm: 1.6; SizeY_mm: 0.8; SizeZ_mm: 1; Value2: 0.1W; SizeArea_mm2: 1.28; AEC Qualified: N; VDC_V: 75V; AEC Category: Q200; SizeAreaWB_mm2: 4.68
R14 R16 R31 R64 = CMP-0022684-3: RES, 10.0 k, 1%, 0.1 W, 0603; Manufacturer: Panasonic; Power_W: 100mW; TempCo: 100 ppm/C; Value_Code: 10k0; U/M: EA; Value: 10.0k; EIA_Code: E96; Res_ohm: 10k; SizeX_mm: 1.6; SizeY_mm: 0.8; SizeZ_mm: 1; Value2: 0.1W; SizeArea_mm2: 1.28; VDC_V: 75V; AEC Category: Q200
R15 R17 R18 = CRCW1206330KJNEA: RES SMD 330K OHM 1% 1/4W 1206; Manufacturer: Yageo; CompType: Resistor; Res_ohm: 330000; Tolerance_%: 5; Value1: 5%; Power_W: 0.25; Value2: 0.25W; VDC_V: 200; TempCo: 200 ppm/C; SizeArea_mm2: 5.12; SizeX_mm: 3.2; SizeY_mm: 1.6; SizeZ_mm: 1.35; EIA_Code: E24; U/M: EA; AEC Category: Q200
R19-R21 = CMP-0018570-2: RES, 0.01, 1%, 1 W, 1206; Manufacturer: Vishay-Dale; Power_W: 1W; TempCo: 75 ppm/C; Value_Code: R010; U/M: EA; Value: 0.01; EIA_Code: E96; SizeX_mm: 3.2; SizeY_mm: 1.6; SizeZ_mm: 1.35; SizeArea_mm2: 5.12; AEC Category: Q200
R25 R36 R39 R41 R43 R44 = CRCW060310K0FKEA: RES, 10.0 k, 1%, 0.1 W, 0603; Manufacturer: Vishay-Dale; Power_W: 0.1; TempCo: 100 ppm/C; Value_Code: 10k0; U/M: EA; Value: 10.0k; EIA_Code: E96; Tolerance_%: 1; Res_ohm: 10000; SizeX_mm: 1.6; SizeY_mm: 0.8; SizeArea_mm2: 1.28; CompType: Resistor; VDC_V: 75; AEC Category: Q200; Value2: 0.1W; Green_Lifecycle: Active; Green_REACh: Passed
R26 R27 R29 R30 R42 R48 R54 R60 R66 = CMP-0022680-4: RES, 1.00 k, 1%, 0.1 W, 0603; Manufacturer: Panasonic; Power_W: 100mW; TempCo: 100 ppm/C; Value_Code: 1k00; U/M: EA; Value: 1.00k; EIA_Code: E96; Res_ohm: 1k; SizeX_mm: 1.6; SizeY_mm: 0.8; SizeZ_mm: 1; SizeArea_mm2: 1.28; VDC_V: 75V; AEC Category: Q200; Value2: 0.1W
R28 = CRCW060350R0FKEA: RES, 50, 1%, 0.1 W, 0603; Manufacturer: Vishay-Dale; CompType: Resistor; Value: 50; Value_Code: 50R0; Tolerance_%: 1; Power_W: 0.1; Value2: 0.1W; VDC_V: 75; TempCo: 100 ppm/C; SizeArea_mm2: 1.28; SizeX_mm: 1.6; SizeY_mm: 0.8; U/M: EA; AEC Category: Q200; Green_Lifecycle: Active; Green_REACh: Passed
R32 = CMP-0023168-5: RES, 51.1, 1%, 0.1 W, 0603; Manufacturer: Yageo; Power_W: 100mW; TempCo: 100 ppm/C; Value_Code: 51R1; Value: 51.1; EIA_Code: E96; SizeX_mm: 1.6; SizeY_mm: 0.8; SizeZ_mm: 1; Value2: 0.1W; SizeArea_mm2: 1.28; AEC Qualified: N; VDC_V: 75V; AEC Category: Q200; SizeAreaWB_mm2: 4.68
R33 = CMP-0022632-1: RES, 88.7 k, 1%, 0.1 W, 0603; Manufacturer: Vishay-Dale; Power_W: 100mW; TempCo: 100 ppm/C; Value_Code: 88k7; U/M: EA; Value: 88.7k; EIA_Code: E96; SizeX_mm: 1.6; SizeY_mm: 0.8; SizeZ_mm: 1; Value2: 0.1W; SizeArea_mm2: 1.28; VDC_V: 75V; AEC Category: Q200
R37 = CMP-0023166-5: RES, 51.1 k, 1%, 0.1 W, 0603; Manufacturer: Yageo; Power_W: 100mW; TempCo: 100 ppm/C; Value_Code: 51k1; Value: 51.1k; EIA_Code: E96; SizeX_mm: 1.6; SizeY_mm: 0.8; SizeZ_mm: 1; Value2: 0.1W; SizeArea_mm2: 1.28; AEC Qualified: N; VDC_V: 75V; AEC Category: Q200; SizeAreaWB_mm2: 4.68
R40 R45 = CMP-0022692-1: RES, 22.0 k, 1%, 0.1 W, AEC-Q200 Grade 0, 0603; Manufacturer: Panasonic; Power_W: 100mW; TempCo: 100 ppm/C; Value_Code: 22k0; U/M: EA; Value: 22.0k; Res_ohm: 22k; SizeX_mm: 1.6; SizeY_mm: 0.8; SizeZ_mm: 1; Value2: 0.1W; SizeArea_mm2: 1.28; AEC Qualified: Y; VDC_V: 50V; AEC Grade: 0; AEC Category: Q200
R46 = CMP-0023148-5: RES, 4.30 k, 1%, 0.1 W, 0603; Manufacturer: Yageo; Power_W: 100mW; TempCo: 100 ppm/C; Value_Code: 4k30; Value: 4.30k; Res_ohm: 4.3k; SizeX_mm: 1.6; SizeY_mm: 0.8; SizeZ_mm: 1; Value2: 0.1W; SizeArea_mm2: 1.28; AEC Qualified: N; VDC_V: 75V; AEC Category: Q200; SizeAreaWB_mm2: 4.68
R47 = CMP-0022708-3: RES, 7.50 k, 1%, 0.1 W, 0603; Manufacturer: Panasonic; Power_W: 100mW; TempCo: 100 ppm/C; Value_Code: 7k50; U/M: EA; Value: 7.50k; EIA_Code: E96; Res_ohm: 7.5k; SizeX_mm: 1.6; SizeY_mm: 0.8; SizeZ_mm: 1; Value2: 0.1W; SizeArea_mm2: 1.28; VDC_V: 75V; AEC Category: Q200
R49 = CRCW060321K5FKEA: RES, 21.5k ohm, 1%, 0.1W, 0603; Manufacturer: Vishay-Dale; CompType: Resistor; Res_ohm: 21500; Value_Code: 21k5; Tolerance_%: 1; Power_W: 0.1; VDC_V: 75; TempCo: 100 ppm/C; EIA_Code: E96; U/M: EA
R50 = CMP-0022680-4: RES, 100 k, 1%, 0.1 W, 0603; Manufacturer: Panasonic; Power_W: 100mW; TempCo: 100 ppm/C; U/M: EA; EIA_Code: E96; SizeX_mm: 1.6; SizeY_mm: 0.8; SizeZ_mm: 1; SizeArea_mm2: 1.28; CompType: Resistor; VDC_V: 75V; AEC Category: Q200; Value2: 0.1W
R52 R55 R61 R63 = CMP-0022109-3: RES, 1.00 k, 1%, 0.1 W, 0603; Manufacturer: Vishay-Dale; Power_W: 100mW; TempCo: 100 ppm/C; Value_Code: 1k00; U/M: EA; Value: 1.00k; EIA_Code: E96; Res_ohm: 1k; SizeX_mm: 1.6; SizeY_mm: 0.8; SizeZ_mm: 1; Value2: 0.1W; SizeArea_mm2: 1.28; VDC_V: 75V; AEC Category: Q200
R53 R62 = RC0603FR-0743KL: RES, 43.0 k, 1%, 0.1 W, 0603; Manufacturer: Yageo America; Power_W: 0.1; TempCo: 200 ppm/C; Value_Code: 43k0; Value: 43.0k; Tolerance_%: 1; Res_ohm: 43000; SizeX_mm: 1.6; SizeY_mm: 0.8; Value2: 0.1W; SizeArea_mm2: 1.28; CompType: Resistor; VDC_V: 150; AEC Category: Q200; Green_Lifecycle: Active; Green_REACh: Passed; U/M: EA
R57 = CMP-0023108-4: RES, 430 k, 1%, 0.1 W, 0603; Manufacturer: Yageo; Power_W: 100mW; TempCo: 100 ppm/C; Value: 430k; SizeX_mm: 1.6; SizeY_mm: 0.8; SizeZ_mm: 1; Value2: 0.1W; SizeArea_mm2: 1.28; AEC Qualified: N; VDC_V: 75V; AEC Category: Q200; SizeAreaWB_mm2: 4.68
R58 R68 = CMP-0022680-4: RES, 2.2 k, 1%, 0.1 W, 0603; Manufacturer: Panasonic; Power_W: 100mW; TempCo: 100 ppm/C; Value_Code: 2k2; U/M: EA; EIA_Code: E96; SizeX_mm: 1.6; SizeY_mm: 0.8; SizeZ_mm: 1; SizeArea_mm2: 1.28; CompType: Resistor; VDC_V: 75V; AEC Category: Q200; Value2: 0.1W
R65 = CMP-0022906-5: RES, 20.0 k, 1%, 0.1 W, 0603; Manufacturer: Yageo; Power_W: 100mW; TempCo: 100 ppm/C; Value_Code: 20k0; Value: 20.0k; EIA_Code: E96; Res_ohm: 20k; SizeX_mm: 1.6; SizeY_mm: 0.8; SizeZ_mm: 1; Value2: 0.1W; SizeArea_mm2: 1.28; AEC Qualified: N; VDC_V: 75V; AEC Category: Q200; SizeAreaWB_mm2: 4.68
RT1 = B59751B0120A070: Thermistor NTC, 50 ohm, 25%, D23 x T10mm, P7.8mm; Manufacturer: Ametherm; Value: 50; Tolerance_%: 25; TaMin_C: -40; TaMax_C: 125; U/M: EA
RV1 = S10K275E2: Varistor 275V RMS 10MM Radial, TH; Manufacturer: EPCOS Inc; SymbolCreator: a0412235
T1 = CMP-0030623-1: Transformer, 105uH, TH; Manufacturer: Wurth Elektronik; Green_Lifecycle: Active; DCR_ohm: 0.06; Green_REACh: Passed; Lp: 105; Ns1toNp: 1.1; Ind_H: 105µH
TP1 = CMP-0055138-1: Test Point, Miniature, Black, TH; Manufacturer: Keystone; CNHeader: FALSE; Green_Lifecycle: Active; Green_REACh: Passed; ContactFinish: Silver; CT: TRUE
TP2 TP3 = CMP-0055137-1: Test Point, Miniature, Red, TH; Manufacturer: Keystone; CNHeader: FALSE; Green_Lifecycle: Active; Green_REACh: Passed; ContactFinish: Silver; CT: TRUE
TP4-TP7 = CMP-0055141-1: Test Point, Miniature, Yellow, TH; Manufacturer: Keystone; CNHeader: FALSE; Green_Lifecycle: Active; Green_REACh: Passed; ContactFinish: Silver; CT: TRUE
TP8-TP13 = 0312-0-15-15-34-27-10-0: Pin Receptacle, .032-.046" .075" Dia, Gold, TH; Manufacturer: Mill-Max; Gender: Female
U1 = CMP-0013026-3: 4-A, 6-A, 3.0-kVRMS Isolated Dual-Channel Gate Driver, D0016A (SOIC-16); Alternate Manufacturer: Texas Instruments; SizeX_mm: 6; SizeZ_mm: 1.75; CompType: IC; U/M: EA; SizeY_mm: 9.9; SizeArea_mm2: 59.4; SizeAreaWB_mm2: 95.2; AEC Category: Q200
U2 = CMP-0861047-2: 50-MHz, Low-Power, Gain of 6-V/V Stable, Rail-to-Rail Output CMOS Operational Amplifier, DBV0005A (SOT-23-5); Manufacturer: Texas Instruments; AEC Category: Q200; SizeY_mm: 2.9; SizeArea_mm2: 8.12; SizeX_mm: 2.8; SizeZ_mm: 1.45; SizeAreaWB_mm2: 14.82; AEC Qualified: N; CompType: IC
U3 = CMP-0081091-1: 5-kVRMS, 3-A Single Channel Isolated Gate Driver with Opto Compatible Input, DWY0006A (SOIC-6); Alternate Manufacturer: Texas Instruments; SizeAreaWB_mm2: 90.18; SizeZ_mm: 3.43; SizeX_mm: 11.5; SizeY_mm: 4.68; SizeArea_mm2: 53.82; CompType: IC; AEC Qualified: N; AEC Category: Q200
U4 U6 = CMP-0068313-2: Low Power Dual Operational Amplifier, 8-pin Narrow SOIC; Manufacturer: Texas Instruments; CompType: IC; AEC Category: Q200; AEC Qualified: N; SizeAreaWB_mm2: 56.58; SizeArea_mm2: 30.38; SizeX_mm: 4.9; SizeY_mm: 6.2; SizeZ_mm: 1.75
U5 = CMP-0065423-1: 4.5ns Rail-to-Rail Comparator, D0008A (SOIC-8); Alternate Manufacturer: Texas Instruments; SizeAreaWB_mm2: 56.58; U/M: EA; SizeZ_mm: 1.75; SizeX_mm: 4.9; SizeY_mm: 6.2; SizeArea_mm2: 30.38; CompType: IC
U12 = CMP-0076095-1: Low-Noise 1 A, 420 kHz Transformer Driver, DBV0006A (SOT-23-6); Alternate PartNumber: SN6505BDBVT; Manufacturer: Texas Instruments; SizeArea_mm2: 8.12; SizeAreaWB_mm2: 14.82; SizeX_mm: 2.8; SizeY_mm: 2.9; SizeZ_mm: 1.45; CompType: IC; U/M: EA; Green_Lifecycle: Active; Green_REACh: Passed
U13 U14 = CMP-0051320-2: Single Power Supply, Single BUFFER GATE w/ 3-State Output (active low enable), DBV0005A (SOT-23-5); Manufacturer: Texas Instruments; Schmitt Trigger: No; Voltage(Nom)(V): 1.8,2.5,3.3,5.5; Output Drive (IOL/IOH)(Max)(mA): 8/-8; Bits(#): 1; F @ Nom Voltage(Max)(Mhz): 50; Output Type: CMOS; Input Type: TTL; VCC(Min)(V): 1.6; tpd @ Nom Voltage(Max)(ns): 14.5,9.5,8.0,6.5; 3-State Output: Yes; ICC @ Nom Voltage(Max)(mA): 0.01; Rating: Catalog; Logic: True; Special Features: 1.8V to 3.3V Up Translation,3.3V to 1.8V Down Translation,5V Input Tolerant; VCC(Max)(V): 5.5; AEC Category: Q200; AEC Qualified: N; CompType: IC; SizeAreaWB_mm2: 14.82; SizeArea_mm2: 8.12; SizeX_mm: 2.8; SizeY_mm: 2.9; SizeZ_mm: 1.45

## Sheet xTIDA-010203; Cover Page.SchDoc
size A4; Date: Not shown in title block; ApprovedBy: Not shown in title block; CheckedBy: Not shown in title block; Author: Not shown in title block; CompanyName: Not shown in title block; Engineer: Not shown in title block; Organization: Not shown in title block; Address1: Not shown in title block; Address2: Not shown in title block; Address3: Not shown in title block; Address4: Not shown in title block; DocumentNumber: 2; Revision: Use project parameter SCH_Rev; SheetNumber: 2; SheetTotal: 3; PageSetup: Record=PageOptions¦CenterHorizontal=True¦CenterVertical=True¦PrintScale=1.00¦XCorrection=1.00¦YCorrection=1.00¦PrintKind=0¦BorderSize=5000000¦LeftOffset=0¦BottomOffset=0¦Orientation=2¦PaperLength=1000¦PaperWidth=1000¦Scale=100¦PaperSource=15¦PrintQuality=600¦MediaType=1¦DitherType=10¦PaperKind=Letter¦PrintScaleMode=1
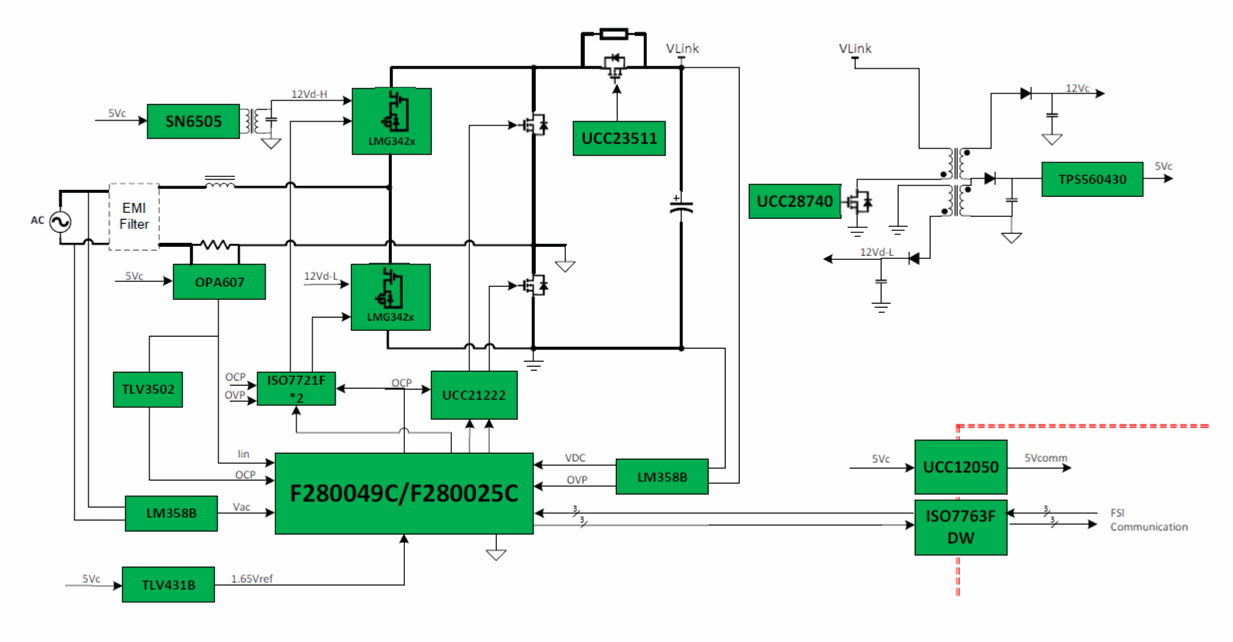
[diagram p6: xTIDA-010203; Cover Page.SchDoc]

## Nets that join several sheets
1V65-ref: xTIDA-010203; CCMTLPFC_AuxP_UCC28740 (5 pins), xTIDA-010203; CCMTLPFC_ControlStage (R69.2 R70.1), xTIDA-010203; CCMTLPFC_PowerStage (6 pins)
5Vc: xTIDA-010203; CCMTLPFC_AuxP_UCC28740 (5 pins), xTIDA-010203; CCMTLPFC_ControlStage (12 pins), xTIDA-010203; CCMTLPFC_PowerStage (25 pins)
12V_L: xTIDA-010203; CCMTLPFC_AuxP_UCC28740 (C61.1 R98.2 U11.1), xTIDA-010203; CCMTLPFC_PowerStage (C25.1 U1.11)
12Vc: xTIDA-010203; CCMTLPFC_AuxP_UCC28740 (C58.1 L7.1 U9.4 U9.5), xTIDA-010203; CCMTLPFC_PowerStage (Brd1.9 C17.1 J4.2 U1.16)
B+: xTIDA-010203; CCMTLPFC_AuxP_UCC28740 (Brd2.7), xTIDA-010203; CCMTLPFC_PowerStage (8 pins)
B-: xTIDA-010203; CCMTLPFC_AuxP_UCC28740 (6 pins), xTIDA-010203; CCMTLPFC_PowerStage (14 pins)
GND-c: xTIDA-010203; CCMTLPFC_AuxP_UCC28740 (9 pins), xTIDA-010203; CCMTLPFC_ControlStage (29 pins), xTIDA-010203; CCMTLPFC_PowerStage (64 pins)
12V_ISO: xTIDA-010203; CCMTLPFC_AuxP_UCC28740 (Brd2.3 Brd2.4 L7.4), xTIDA-010203; CCMTLPFC_PowerStage (TP7.1)
ANA_Iac: xTIDA-010203; CCMTLPFC_ControlStage (J2.18), xTIDA-010203; CCMTLPFC_PowerStage (C18.2 R28.2)
ANA_Vac: xTIDA-010203; CCMTLPFC_ControlStage (J2.20), xTIDA-010203; CCMTLPFC_PowerStage (C34.2 R42.1)
ANA_Vdc: xTIDA-010203; CCMTLPFC_ControlStage (J2.24), xTIDA-010203; CCMTLPFC_PowerStage (C44.2 R60.1)
GaN_FLT_H: xTIDA-010203; CCMTLPFC_ControlStage (J2.74), xTIDA-010203; CCMTLPFC_PowerStage (Brd1.6 J5.3)
GaN_FLT_L: xTIDA-010203; CCMTLPFC_ControlStage (J2.76), xTIDA-010203; CCMTLPFC_PowerStage (Brd1.3 J4.5)
GaN_OC_H: xTIDA-010203; CCMTLPFC_ControlStage (J2.70), xTIDA-010203; CCMTLPFC_PowerStage (Brd1.4 J5.2)
GaN_OC_L: xTIDA-010203; CCMTLPFC_ControlStage (J2.72), xTIDA-010203; CCMTLPFC_PowerStage (Brd1.5 J4.4)
LF-MOSH: xTIDA-010203; CCMTLPFC_ControlStage (J2.49), xTIDA-010203; CCMTLPFC_PowerStage (R26.2)
LF-MOSL: xTIDA-010203; CCMTLPFC_ControlStage (J2.51), xTIDA-010203; CCMTLPFC_PowerStage (R29.2)
PFCG_1H: xTIDA-010203; CCMTLPFC_ControlStage (R74.1), xTIDA-010203; CCMTLPFC_PowerStage (U13.2)
PFCG_1L: xTIDA-010203; CCMTLPFC_ControlStage (R76.1), xTIDA-010203; CCMTLPFC_PowerStage (U14.2)
RELAY_CTRL: xTIDA-010203; CCMTLPFC_ControlStage (J2.67), xTIDA-010203; CCMTLPFC_PowerStage (R105.2)
TEMP_H: xTIDA-010203; CCMTLPFC_ControlStage (J2.9), xTIDA-010203; CCMTLPFC_PowerStage (Brd1.2 J5.1)
TEMP_L: xTIDA-010203; CCMTLPFC_ControlStage (J2.11), xTIDA-010203; CCMTLPFC_PowerStage (Brd1.7 J4.3)

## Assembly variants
001: not fitted R132 R133 R134 R612 R613 R615 R619 U602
